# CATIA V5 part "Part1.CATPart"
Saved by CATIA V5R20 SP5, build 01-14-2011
Part number: Part1
Bounding box of the stored display mesh (mm): x -20.115 to 20, y 0 to 79.532, z 0 to 38
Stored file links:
  C:\Documents and Settings\Student\桌面\Part1.CATPart
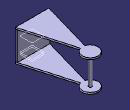
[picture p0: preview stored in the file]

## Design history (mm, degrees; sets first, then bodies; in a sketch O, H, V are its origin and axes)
Body1 (main body)
  Sketch1 on xy-plane, origin (0, 0, 0), H (1, 0, 0), V (0, 1, 0)
    line L1 (-20, 0) -> (20, 0)
    point P1 (-20, 0)
    point P3 (0, 70)
    line L2 (2.6185, 60.8351) -> (20, 0)
    arc A1 centre (0, 70) radius 9.5316 from (2.6185, 60.8351) to (-2.6185, 60.8351) ccw
    line L3 (-2.6185, 60.8351) -> (-20, 0)
    distance P3 L1 = 70
    distance P3 V = 0
    coincidence: P1 H
    horizontal: L1 H
  Pad1: profile Sketch1, direction (0, 0, 1), length 2
  Plane1: type Offset, RefPlane xy-plane, Offset 2
  Sketch2 on Plane1, origin (0, 0, 2), H (1, 0, 0), V (0, 1, 0)
    circle A1 centre (0, 70) radius 2
    point P1 (0, 70)
    point P2 (0, 72)
    point P3 (19.5991, 0)
    line L1 (19.5991, 0) -> (-20.115, 0)
    line L2 (-20.115, 0) -> (-19.5707, 1.7153)
    line L3 (-19.5707, 1.7153) -> (19.5991, 1.7153)
    line L4 (19.5991, 1.7153) -> (19.5991, 0)
    distance P1 H = 70
    coincidence: P1 V, A1 P2, P2 V, P3 H
    horizontal: L1 H, L3 H
    tangency: L2 A1
    vertical: L4 V
  Pad2: profile Sketch2, direction (0, 0, 1), length 34
  Plane2: type Offset, RefPlane Plane1, Offset 17
  Mirror1: of the body so far, about Plane2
